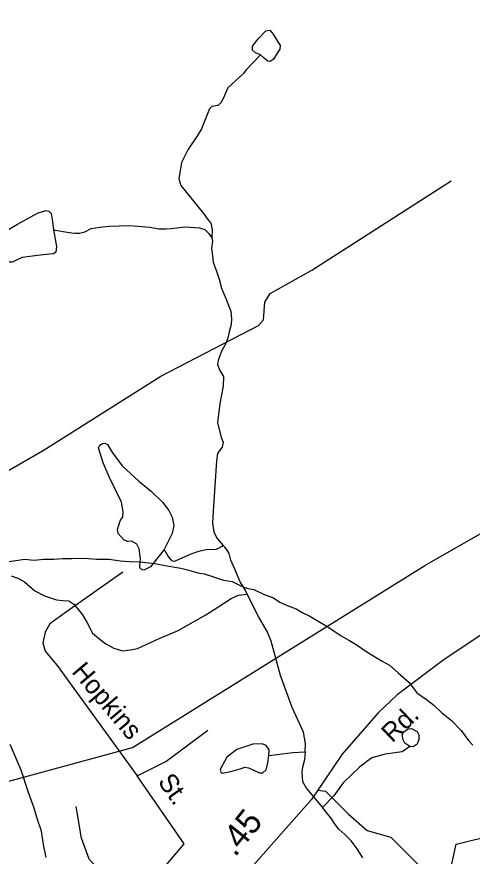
# Model space of a CAD drawing. Extents: x 2056842 to 2160602, y 826753 to 1016856.
# Drawn here: x 2081629 to 2083938, y 892991 to 897244 of the extents above; entities that cross this region are included whole.
import ezdxf

# ---------------------------------------------------------------- set-up
doc = ezdxf.new("R2010")
doc.units = 0
for name, color, linetype in [('Exist Boundary Political City Limit New', 7, 'Continuous'), ('Exist Hydrographic Creek Single Shore', 7, 'Continuous'), ('Exist Hydrographic Misc Water Feature', 7, 'Continuous'), ('Exist Railroad Mainline', 7, 'Continuous'), ('Exist Road Non-System Type 51', 7, 'Continuous'), ('Exist Road Non-System Type 51 Label', 7, 'Continuous'), ('Exist Road Secondary Mileage Hundredths English Label', 7, 'Continuous'), ('Exist Road Secondary Type 51 Attributed', 7, 'Continuous'), ('Exist Road Secondary Type 51 Label', 7, 'Continuous'), ('Exist Utilities Electrical Transmission Line', 7, 'Continuous'), ('Map Preparation Boundary City Limit Buffer Line', 7, 'Continuous')]:
    doc.layers.add(name, color=color, linetype=linetype)

msp = doc.modelspace()

# ---------------------------------------------------------------- linework, layer by layer
at = {"layer": 'Exist Boundary Political City Limit New'}
msp.add_lwpolyline([(2081576.9, 894481.8), (2081636.9, 894490), (2081668.9, 894496.1), (2081716.9, 894490.1), (2081764.8, 894496.4), (2081816.8, 894496.5), (2081860.9, 894498.6), (2081908.9, 894498.8), (2081970.9, 894501.1), (2082032.8, 894495.2), (2082096.8, 894495.5), (2082152.8, 894487.5), (2082200.9, 894483.7), (2082252.9, 894481.9), (2082328.9, 894474.1), (2082380.9, 894464.2), (2082460.9, 894449.5), (2082500.9, 894440.7), (2082546.9, 894426.8), (2082579, 894420.9), (2082617, 894409.1), (2082677, 894389.3), (2082721, 894383.4), (2082765.2, 894361.5), (2082801.1, 894347.7), (2082831.2, 894341.7), (2082879.4, 894317.9), (2082931.4, 894300), (2082963.4, 894278.2), (2082999.4, 894260.2), (2083045.4, 894244.5), (2083075.4, 894226.4), (2083115.6, 894206.6), (2083151.6, 894184.7), (2083211.6, 894149), (2083273.9, 894107.1), (2083311.9, 894085.3), (2083354, 894059.5), (2083398, 894029.5), (2083448.2, 893999.7), (2083482.1, 893979.8), (2083518.4, 893957.9), (2083562.4, 893920.1), (2083618.5, 893870.2), (2083656.6, 893818.4), (2083706.8, 893784.5), (2083742.8, 893756.6), (2083783, 893718.8), (2083833.1, 893678.9), (2083881.4, 893627.1), (2083919.4, 893577.1), (2083941.4, 893553.3)], dxfattribs=at)
at = {"layer": 'Exist Hydrographic Creek Single Shore'}
for points in [[(2082864.6, 897050.6), (2082790.1, 896973), (2082778.6, 896956.9), (2082698.6, 896884.6), (2082681.7, 896844.4), (2082665.5, 896809.5), (2082648, 896794.5), (2082618.1, 896789.5), (2082606.9, 896777), (2082565.7, 896675.7), (2082545.8, 896642), (2082495.9, 896569.6), (2082463.4, 896505.9), (2082450.9, 896423.6), (2082460.9, 896389.9), (2082576.4, 896248.1), (2082596.5, 896218.3), (2082612.7, 896198.4), (2082619.1, 896164.5), (2082618.7, 896124.5)], [(2082618.7, 896124.5), (2082620.7, 896106.3), (2082616.8, 896070.3), (2082621.1, 896032.4), (2082625.2, 896000.5), (2082643.3, 895950.7), (2082655.6, 895914.8), (2082667.5, 895868.8), (2082691.9, 895808.6), (2082714, 895752.9), (2082718.5, 895712.9), (2082716.3, 895684.8), (2082706.4, 895648.5), (2082698.6, 895616.9), (2082688.4, 895588.8), (2082668.9, 895552.8), (2082657, 895522.5), (2082650.6, 895502.4), (2082647, 895482.6), (2082658.9, 895452.4), (2082677.1, 895420.9), (2082675.5, 895372.8), (2082658.8, 895284.3), (2082646.3, 895188.1), (2082665, 895112.3), (2082676.2, 895088.5), (2082670, 895063.6), (2082658.8, 895047.4), (2082646.3, 895031.1), (2082641.3, 894993.7), (2082625, 894738.5), (2082621.3, 894678.6), (2082627.7, 894634.7), (2082643.7, 894602.6), (2082675.5, 894564.8)], [(2082796.4, 894319), (2082788.2, 894336.9), (2082762.2, 894380.8), (2082734, 894444.7), (2082714, 894490.7), (2082705.8, 894524.7), (2082695.6, 894540.6), (2082683.5, 894556.6), (2082675.5, 894564.7)], [(2083090.9, 893519.4), (2083092.1, 893562.6), (2083083.4, 893620), (2083024.8, 893745), (2082966.6, 893906.3), (2082919.2, 894081), (2082899.3, 894129.7), (2082853.9, 894204.6), (2082796.4, 894319)], [(2083090.9, 893519.4), (2083087.1, 893478.2), (2083078.4, 893442), (2083073.4, 893415.8), (2083077.2, 893369.6), (2083098.4, 893334.6), (2083178.2, 893237)], [(2083384.3, 892982.9), (2083354.4, 893028.8), (2083324, 893068.8), (2083292.2, 893100.6), (2083261.9, 893128.5), (2083239.9, 893156.5), (2083225.9, 893178.5), (2083178.2, 893237)]]:
    msp.add_lwpolyline(points, dxfattribs=at)
at = {"layer": 'Exist Hydrographic Misc Water Feature'}
for points in [[(2082864.6, 897050.6), (2082839.7, 897060.6), (2082823.4, 897075.6), (2082824.7, 897095.6), (2082852.1, 897133), (2082892, 897172.9), (2082912, 897175.4), (2082929.5, 897156.7), (2082964.4, 897099.3), (2082961.9, 897080.6), (2082929.5, 897026.9), (2082914.5, 897016.9), (2082902, 897019.4), (2082877.1, 897039.4), (2082864.6, 897050.6)], [(2081816, 896164.7), (2081829.7, 896079.8), (2081827.2, 896051.1), (2081816, 896043.6), (2081794.8, 896041.1), (2081733.7, 896034.9), (2081656.3, 896023.7), (2081605.2, 896001.2), (2081572.8, 896001.2), (2081515.4, 896012.4), (2081465.5, 896038.6), (2081456.7, 896057.4), (2081463, 896084.8), (2081482.9, 896102.3), (2081550.3, 896143.5), (2081632.6, 896193.4), (2081733.7, 896248.3), (2081776.1, 896263.3), (2081792.3, 896258.3), (2081803.5, 896247.1), (2081811, 896205.9), (2081816, 896164.7)], [(2081816, 896164.7), (2081894.6, 896150.2), (2081922.9, 896148.4), (2081947.1, 896148.3), (2081974.8, 896154.3), (2082006.8, 896170.6), (2082050.7, 896178.5), (2082096.8, 896182.9), (2082148.5, 896184.7), (2082194.8, 896187.1), (2082244.9, 896183.2), (2082302.9, 896177.6), (2082350.9, 896169.6), (2082386.5, 896169.8), (2082411.1, 896171.7), (2082482.7, 896180), (2082554.7, 896174.3), (2082582.8, 896166.4), (2082602.9, 896146.3), (2082618.7, 896124.5)], [(2082375.9, 894544.3), (2082307.2, 894457), (2082273.6, 894440.8), (2082259.8, 894444.5), (2082253.6, 894452), (2082253.6, 894464.5), (2082256.1, 894498.2), (2082249.9, 894548.1), (2082237.4, 894571.8), (2082211.2, 894586.8), (2082190, 894585.5), (2082172.5, 894594.3), (2082143.8, 894625.5), (2082140.1, 894646.7), (2082153.8, 894690.4), (2082166.3, 894710.4), (2082168.8, 894735.3), (2082160, 894785.2), (2082097.7, 894912.6), (2082066.5, 894983.7), (2082044, 895059.8), (2082050.3, 895073.6), (2082064, 895082.3), (2082077.7, 895083.5), (2082088.9, 895076.1), (2082115.1, 895034.9), (2082163.8, 894968.7), (2082248.6, 894891.3), (2082312.2, 894838.9), (2082367.1, 894785.2), (2082400.8, 894742.8), (2082417, 894707.9), (2082424.5, 894666.7), (2082417, 894625.5), (2082375.9, 894544.3)], [(2082375.9, 894544.3), (2082396.2, 894509.9), (2082409.7, 894491.9), (2082422.8, 894484.9), (2082433.7, 894487.9), (2082456.3, 894497.9), (2082480, 894508.1), (2082513.9, 894522.5), (2082551.8, 894536.1), (2082595.9, 894546.5), (2082636.1, 894544.5), (2082655.8, 894552.8), (2082667.7, 894560.8), (2082675.5, 894564.8)], [(2081600.2, 894411.8), (2081635.1, 894399.3), (2081667.6, 894380.6), (2081720, 894335.7), (2081769.8, 894309.4), (2081831, 894289.5), (2081863.4, 894287), (2081893.3, 894284.5), (2081918.3, 894268.3), (2081962.7, 894214.4), (2081985.1, 894176.6), (2082013.1, 894120.8), (2082051.1, 894089), (2082081.4, 894067), (2082121.9, 894044.8), (2082165.5, 894031.1), (2082205.5, 894035.6), (2082241.6, 894043.5), (2082347.4, 894091.6), (2082447, 894134.1), (2082588.4, 894213.3), (2082653.3, 894255.8), (2082715.7, 894297), (2082752.6, 894312.9), (2082796.4, 894318.9)], [(2083622, 893546.6), (2083597.1, 893562.8), (2083588.4, 893580.3), (2083583.4, 893605.2), (2083590.9, 893620.2), (2083613.3, 893636.4), (2083630.8, 893637.7), (2083658.2, 893622.7), (2083668.2, 893605.2), (2083668.2, 893582.8), (2083658.2, 893559.1), (2083638.3, 893545.3), (2083622, 893546.6)], [(2082906.3, 893501.4), (2082908.8, 893528.9), (2082893.8, 893551.3), (2082873.8, 893560.1), (2082825.2, 893558.8), (2082744.1, 893531.4), (2082694.2, 893492.7), (2082660.5, 893430.3), (2082663, 893416.5), (2082670.5, 893411.5), (2082714.2, 893420.3), (2082761.6, 893434), (2082785.3, 893442.7), (2082804, 893439), (2082860.1, 893414), (2082876.3, 893414), (2082893.8, 893429), (2082902.5, 893464), (2082906.3, 893501.4)], [(2083622, 893546.6), (2083583.4, 893520.4), (2083496.1, 893507.9), (2083429.9, 893489.2), (2083366.3, 893441.7), (2083283.6, 893362.8), (2083235.7, 893296.7), (2083178.2, 893237)], [(2082906.3, 893501.4), (2083028.5, 893516.4), (2083090.9, 893519.4)]]:
    msp.add_lwpolyline(points, dxfattribs=at)
at = {"layer": 'Exist Railroad Mainline'}
msp.add_lwpolyline([(2081777.5, 892984.5), (2081765.4, 893050.6), (2081755, 893118.4), (2081733, 893182.5), (2081716.8, 893234.4), (2081688.5, 893314.2), (2081652.2, 893426.2), (2081595.9, 893556)], dxfattribs=at)
at = {"layer": 'Exist Road Non-System Type 51'}
for points in [[(2081084.3, 894953.1), (2081215.3, 894948.7), (2081498.3, 894929.3), (2081583.2, 894944.2), (2081767.9, 895050), (2082360, 895423.4), (2082855.3, 895680.5), (2082880.6, 895708.9), (2082886.6, 895798.3), (2082913.4, 895841.5), (2083124.9, 895959.3), (2083831.7, 896413.2)], [(2082166.1, 894429.2), (2081881.6, 894229.4), (2081796.9, 894168.8), (2081772.7, 894126.4), (2081760.6, 894071.9), (2081772.7, 894029.5), (2081833.2, 893956.8), (2082239.4, 893397.7)], [(2082183.5, 892715.8), (2082323.5, 892870.8), (2082478.5, 893052.7), (2082239.4, 893397.7), (2082385.4, 893470.8), (2082596.9, 893628.8)], [(2083155.2, 893324.6), (2083194.9, 893321), (2083309.6, 893204.7), (2083405, 893121.2), (2083525.6, 893086.9), (2083705.9, 892906.6), (2083819.8, 892882)], [(2081893.1, 892367), (2082183.5, 892715.8), (2082174.6, 892784.4), (2082091.2, 892870.8), (2081995.8, 892975.1), (2081957.1, 893082.5), (2081930.3, 893243.4)], [(2083819.8, 892882), (2083857.1, 893051.9), (2083988.1, 893083.2), (2084143.8, 893149.5), (2084222.7, 893210.7)]]:
    msp.add_lwpolyline(points, dxfattribs=at)
at = {"layer": 'Exist Road Secondary Type 51 Attributed'}
msp.add_lwpolyline([(2086560.8, 895490.5), (2086423, 895420), (2085992.7, 895214.1), (2085136.7, 894740.4), (2084487.3, 894417.8), (2084208.9, 894272.1), (2084014, 894132.8), (2083789.4, 893981.8), (2083557.7, 893809.2), (2083460.7, 893717.6), (2083278.4, 893508.1), (2083123.9, 893278), (2082828.4, 892944.6), (2082621.8, 892721.6), (2082419.7, 892510.4), (2082277.8, 892346.8), (2082143, 892183.2), (2082049.8, 892059.7)], dxfattribs=at)
at = {"layer": 'Exist Utilities Electrical Transmission Line'}
msp.add_lwpolyline([(2081456.5, 893335.6), (2082215.8, 893541.9), (2083698.6, 894464.4), (2090653.3, 898439.9), (2091279.8, 898905.8), (2093655.2, 900217), (2093986.6, 900420.2), (2096731, 902082.7)], dxfattribs=at)
at = {"layer": 'Map Preparation Boundary City Limit Buffer Line'}
msp.add_lwpolyline([(2081576.9, 894481.8), (2081636.9, 894490), (2081668.9, 894496.1), (2081716.9, 894490.1), (2081764.8, 894496.4), (2081816.8, 894496.5), (2081860.9, 894498.6), (2081908.9, 894498.8), (2081970.9, 894501.1), (2082032.8, 894495.2), (2082096.8, 894495.5), (2082152.8, 894487.5), (2082200.9, 894483.7), (2082252.9, 894481.9), (2082328.9, 894474.1), (2082380.9, 894464.2), (2082460.9, 894449.5), (2082500.9, 894440.7), (2082546.9, 894426.8), (2082579, 894420.9), (2082617, 894409.1), (2082677, 894389.3), (2082721, 894383.4), (2082765.2, 894361.5), (2082801.1, 894347.7), (2082831.2, 894341.7), (2082879.4, 894317.9), (2082931.4, 894300), (2082963.4, 894278.2), (2082999.4, 894260.2), (2083045.4, 894244.5), (2083075.4, 894226.4), (2083115.6, 894206.6), (2083151.6, 894184.7), (2083211.6, 894149), (2083273.9, 894107.1), (2083311.9, 894085.3), (2083354, 894059.5), (2083398, 894029.5), (2083448.2, 893999.7), (2083482.1, 893979.8), (2083518.4, 893957.9), (2083562.4, 893920.1), (2083618.5, 893870.2), (2083656.6, 893818.4), (2083706.8, 893784.5), (2083742.8, 893756.6), (2083783, 893718.8), (2083833.1, 893678.9), (2083881.4, 893627.1), (2083919.4, 893577.1), (2083941.4, 893553.3)], dxfattribs=at)

# ---------------------------------------------------------------- texts
at = {"layer": 'Exist Road Non-System Type 51 Label'}
for s, rotation, p in [('Hopkins', 310.2154, (2081903.6, 893923.7)), ('St.', 304.8586, (2082341.1, 893368.6))]:
    msp.add_text(s, height=95, rotation=rotation, dxfattribs=at).set_placement(p)
at = {"layer": 'Exist Road Secondary Mileage Hundredths English Label'}
msp.add_text('.45', height=125, rotation=51.0478, dxfattribs=at).set_placement((2082735.7, 892982.7))
at = {"layer": 'Exist Road Secondary Type 51 Label'}
msp.add_text('Rd.', height=95, rotation=43.5152, dxfattribs=at).set_placement((2083532.6, 893561.6))

doc.saveas('drawing.dxf')
